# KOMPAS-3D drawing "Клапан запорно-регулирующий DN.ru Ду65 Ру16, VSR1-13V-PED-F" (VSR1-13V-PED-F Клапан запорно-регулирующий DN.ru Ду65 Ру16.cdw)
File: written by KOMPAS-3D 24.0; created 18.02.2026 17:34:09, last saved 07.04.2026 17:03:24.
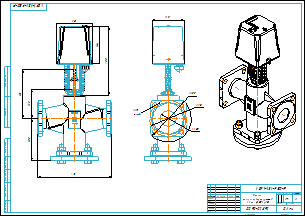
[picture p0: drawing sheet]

Document properties: Автор: R2D2; Форматы листов документа: A2; Полное имя файла: VSR1-13V-PED-F Клапан запорно-регулирующий DN.ru Ду65 Ру16.m3d; Масса: 17.2; Наименование: Клапан запорно-регулирующий DN.ru Ду65 Ру16; Количество листов документа: 1; Примечание: D090-02892

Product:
- Part/product: Клапан запорно-регулирующий DN.ru Ду65 Ру16  | designation VSR1-13V-PED-F
    Масса: 17.2
    Раздел спецификации: Прочие изделия
    Примечание: D090-02892

Views: Вид 1, Спереди
Referenced files in E:\Работа\Зайцев\Солянка\VSR1-13V-PED-F Клапан запорно-регулирующий DN.ru\DN15\DN15 Kv0.16\: VSR1-13V-PED-F Клапан запорно-регулирующий DN.ru Ду15 Ру16.m3d
Referenced files in E:\Работа\Зайцев\Солянка\VSR1-13V-PED-F Клапан запорно-регулирующий DN.ru\DN65\: VSR1-13V-PED-F Клапан запорно-регулирующий DN.ru Ду65 Ру16.m3d
Referenced files in E:\Работа\Зайцев\Для компаса\: чертеж DN.ru А3.cdt
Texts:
  Линейный размер
  VSR1-13V-PED-F
  чертеж DN.ru А3.cdt
  Клапан
  запорно-регулирующий
  DN.ru Ду65 Ру16
  Клапан запорно-регулирующий DN.ru Ду65 Ру16
  VSR1-13V-PED-F Клапан запорно-регулирующий DN.ru Ду65 Ру16
Dimensions and other numbers on the sheet: 0; 3; 2; 4; 143; 144; 269; 165; 115; 290; 190; 9; 1:2; 1; 17,2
